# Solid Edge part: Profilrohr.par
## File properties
Username: ahadarics
Dokumentum tartalom típus: 0
Author: ahadarics
Last saved by: ahadarics
Revision: 78
Sűrűség: 0,000 kg/m^3
Pontosság: 0,990
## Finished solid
Body 1: solid body, 6 faces, 6 edges, 0 vertices.
  Faces by surface: cone 2, cylinder 2, plane 2
  Edges by curve: circle 6
Bounding box of the edges (mm): 33.600 x 33.600 x 98.000, from (-16.8, -16.8, -69) to (16.8, 16.8, 29).
Cylindrical faces by radius (mm): R16 x1, R16.8 x1
Conical faces (half-angle, radius in mm at the cone's reference point): 15 deg R16.067 x2
Planar faces by outward normal: +z 1, -z 1
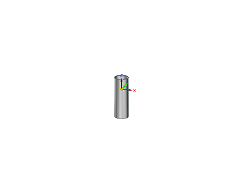
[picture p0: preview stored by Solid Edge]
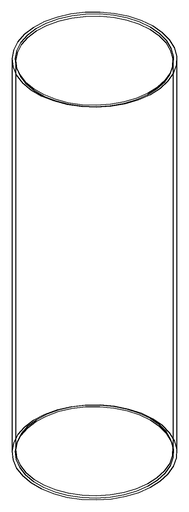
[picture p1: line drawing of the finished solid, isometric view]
